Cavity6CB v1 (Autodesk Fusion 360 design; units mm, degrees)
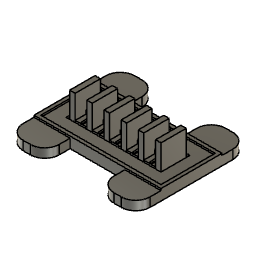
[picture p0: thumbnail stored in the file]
sketch "Sketch1" plane through (0, 0, 0) normal (0, 0, 1) x axis (1, 0, 0)
  line L1 (3, 0) -> (0, 0)
  line L2 (3, 14) -> (3, 0)
  line L3 (0, 14) -> (3, 14)
  line L4 (0, 0) -> (0, 14)
  line L5 (9.5, 14) -> (3, 14)
  line L6 (9.5, 0) -> (9.5, 14)
  line L7 (3, 0) -> (9.5, 0)
  line L8 (9.5, 8) -> (3, 8)
  line L9 (3, 6) -> (3, 8)
  line L10 (9.5, 6) -> (3, 6)
  line L11 (9.5, 6) -> (9.5, 8)
  line L12 (7, 5.5) -> (5.5, 5.5)
  line L13 (7, 0.7) -> (7, 5.5)
  line L14 (5.5, 0.7) -> (7, 0.7)
  line L15 (5.5, 5.5) -> (5.5, 0.7)
  line L16 (12.5, 0) -> (9.5, 0)
  line L17 (12.5, 14) -> (12.5, 0)
  line L18 (9.5, 14) -> (12.5, 14)
  line L19 (9.5, 0) -> (9.5, 14)
  line L20 (19, 14) -> (12.5, 14)
  line L21 (19, 0) -> (19, 14)
  line L22 (12.5, 0) -> (19, 0)
  line L23 (19, 8) -> (12.5, 8)
  line L24 (19, 6) -> (19, 8)
  line L25 (19, 6) -> (12.5, 6)
  line L26 (12.5, 6) -> (12.5, 8)
  line L27 (16.5, 5.5) -> (15, 5.5)
  line L28 (16.5, 0.7) -> (16.5, 5.5)
  line L29 (15, 0.7) -> (16.5, 0.7)
  line L30 (15, 5.5) -> (15, 0.7)
  line L31 (22, 14) -> (19, 14)
  line L32 (22, 0) -> (22, 14)
  line L33 (19, 0) -> (22, 0)
  line L34 (19, 14) -> (19, 0)
  line L35 (28.5, 14) -> (22, 14)
  line L36 (28.5, 0) -> (28.5, 14)
  line L37 (22, 0) -> (28.5, 0)
  line L38 (28.5, 8) -> (22, 8)
  line L39 (28.5, 6) -> (28.5, 8)
  line L40 (22, 6) -> (28.5, 6)
  line L41 (22, 6) -> (22, 8)
  line L42 (26, 0.7) -> (24.5, 0.7)
  line L43 (26, 5.5) -> (26, 0.7)
  line L44 (24.5, 5.5) -> (26, 5.5)
  line L45 (24.5, 0.7) -> (24.5, 5.5)
  line L46 (31.5, 14) -> (28.5, 14)
  line L47 (31.5, 0) -> (31.5, 14)
  line L48 (28.5, 0) -> (31.5, 0)
  line L49 (28.5, 14) -> (28.5, 0)
  line L50 (38, 14) -> (31.5, 14)
  line L51 (38, 0) -> (38, 14)
  line L52 (31.5, 0) -> (38, 0)
  line L53 (38, 8) -> (31.5, 8)
  line L54 (38, 6) -> (38, 8)
  line L55 (31.5, 6) -> (38, 6)
  line L56 (31.5, 6) -> (31.5, 8)
  line L57 (35.5, 0.7) -> (34, 0.7)
  line L58 (35.5, 5.5) -> (35.5, 0.7)
  line L59 (34, 5.5) -> (35.5, 5.5)
  line L60 (34, 0.7) -> (34, 5.5)
  line L61 (41, 14) -> (38, 14)
  line L62 (41, 0) -> (41, 14)
  line L63 (38, 0) -> (41, 0)
  line L64 (38, 14) -> (38, 0)
  line L65 (47.5, 14) -> (41, 14)
  line L66 (47.5, 0) -> (47.5, 14)
  line L67 (41, 0) -> (47.5, 0)
  line L68 (47.5, 8) -> (41, 8)
  line L69 (47.5, 6) -> (47.5, 8)
  line L70 (41, 6) -> (47.5, 6)
  line L71 (41, 8) -> (41, 6)
  line L72 (45, 5.5) -> (43.5, 5.5)
  line L73 (45, 0.7) -> (45, 5.5)
  line L74 (43.5, 0.7) -> (45, 0.7)
  line L75 (43.5, 5.5) -> (43.5, 0.7)
  line L76 (50.5, 14) -> (47.5, 14)
  line L77 (50.5, 0) -> (50.5, 14)
  line L78 (47.5, 0) -> (50.5, 0)
  line L79 (47.5, 14) -> (47.5, 0)
  line L80 (57.5588, 7) -> (-12, 7)
  line L81 (7, 8.5) -> (5.5, 8.5)
  line L82 (5.5, 8.5) -> (5.5, 13.3)
  line L83 (5.5, 13.3) -> (7, 13.3)
  line L84 (7, 13.3) -> (7, 8.5)
  line L85 (16.5, 8.5) -> (15, 8.5)
  line L86 (15, 8.5) -> (15, 13.3)
  line L87 (15, 13.3) -> (16.5, 13.3)
  line L88 (16.5, 13.3) -> (16.5, 8.5)
  line L89 (24.5, 8.5) -> (26, 8.5)
  line L90 (24.5, 13.3) -> (24.5, 8.5)
  line L91 (26, 13.3) -> (24.5, 13.3)
  line L92 (26, 8.5) -> (26, 13.3)
  line L93 (34, 8.5) -> (35.5, 8.5)
  line L94 (34, 13.3) -> (34, 8.5)
  line L95 (35.5, 13.3) -> (34, 13.3)
  line L96 (35.5, 8.5) -> (35.5, 13.3)
  line L97 (45, 8.5) -> (43.5, 8.5)
  line L98 (43.5, 8.5) -> (43.5, 13.3)
  line L99 (45, 13.3) -> (45, 8.5)
  line L100 (43.5, 13.3) -> (45, 13.3)
  line L101 (50.5, 0) -> (0, 0)
  line L102 (50.5, 14) -> (50.5, 0)
  line L103 (0, 14) -> (50.5, 14)
  line L104 (0, 0) -> (0, 14)
  line L105 (-1, 15) -> (51.5, 15)
  line L106 (-1, -1) -> (-1, 15)
  line L107 (51.5, -1) -> (-1, -1)
  line L108 (51.5, 15) -> (51.5, -1)
  line L109 (58.5, -8) -> (-8, -8)
  line L110 (58.5, 22) -> (58.5, -8)
  line L111 (-8, 22) -> (58.5, 22)
  line L112 (-8, -8) -> (-8, 22)
  line L113 (60.4, -9.9) -> (-9.9, -9.9)
  line L114 (60.4, 23.9) -> (60.4, -9.9)
  line L115 (-9.9, 23.9) -> (60.4, 23.9)
  line L116 (-9.9, -9.9) -> (-9.9, 23.9)
  point P1 (0, 0)
  point P2 (0, 0)
  point P8 (3, 8)
  point P9 (9.5, 8)
  point P10 (3, 6)
  point P11 (9.5, 6)
  point P21 (12.5, 8)
  point P23 (19, 6)
  point P24 (12.5, 6)
  point P34 (22, 8)
  point P35 (28.5, 8)
  point P36 (28.5, 6)
  point P37 (22, 6)
  point P47 (31.5, 8)
  point P48 (38, 8)
  point P49 (38, 6)
  point P50 (31.5, 6)
  point P60 (41, 8)
  point P61 (47.5, 8)
  point P62 (47.5, 6)
  point P63 (41, 6)
  point P12 (5.5, 5.5)
  point P73 (5.5, 8.5)
  point P13 (7, 5.5)
  point P74 (7, 8.5)
  point P14 (7, 0.7)
  point P76 (7, 13.3)
  point P15 (5.5, 0.7)
  point P75 (5.5, 13.3)
  point P25 (15, 5.5)
  point P77 (15, 8.5)
  point P26 (16.5, 5.5)
  point P78 (16.5, 8.5)
  point P27 (16.5, 0.7)
  point P80 (16.5, 13.3)
  point P28 (15, 0.7)
  point P79 (15, 13.3)
  point P38 (24.5, 0.7)
  point P83 (24.5, 13.3)
  point P39 (26, 0.7)
  point P84 (26, 13.3)
  point P40 (26, 5.5)
  point P81 (26, 8.5)
  point P41 (24.5, 5.5)
  point P82 (24.5, 8.5)
  point P51 (34, 0.7)
  point P87 (34, 13.3)
  point P52 (35.5, 0.7)
  point P88 (35.5, 13.3)
  point P53 (35.5, 5.5)
  point P85 (35.5, 8.5)
  point P54 (34, 5.5)
  point P86 (34, 8.5)
  point P64 (43.5, 5.5)
  point P89 (43.5, 8.5)
  point P65 (45, 5.5)
  point P90 (45, 8.5)
  point P66 (45, 0.7)
  point P92 (45, 13.3)
  point P67 (43.5, 0.7)
  point P91 (43.5, 13.3)
  point P93 (0, 0)
  point P3 (3, 0)
  point P5 (0, 14)
  point P4 (3, 14)
  point P6 (9.5, 14)
  point P7 (9.5, 0)
  point P16 (12.5, 0)
  point P18 (9.5, 14)
  point P17 (12.5, 14)
  point P19 (19, 14)
  point P29 (22, 14)
  point P32 (28.5, 14)
  point P42 (31.5, 14)
  point P45 (38, 14)
  point P55 (41, 14)
  point P58 (47.5, 14)
  point P68 (50.5, 14)
  point P70 (47.5, 0)
  horizontal L1
  vertical L2
  horizontal L3
  vertical L4
  coincident P1 P2
  perpendicular L2 L5
  perpendicular L3 L6
  perpendicular L2 L7
  coincident L2 P8
  coincident L6 P9
  perpendicular L6 L8
  coincident L2 P10
  coincident L6 P11
  perpendicular L6 L10
  horizontal L12
  vertical L13
  horizontal L14
  vertical L15
  horizontal L16
  vertical L17
  horizontal L18
  vertical L19
  perpendicular L17 L20
  perpendicular L20 L21
  perpendicular L17 L22
  coincident L17 P21
  perpendicular L17 L23
  coincident L21 P23
  perpendicular L23 L24
  coincident L17 P24
  perpendicular L21 L25
  horizontal L27
  vertical L28
  horizontal L29
  vertical L30
  horizontal L31
  vertical L32
  horizontal L33
  vertical L34
  perpendicular L32 L35
  perpendicular L31 L36
  perpendicular L32 L37
  coincident L32 P34
  coincident L36 P35
  perpendicular L36 L38
  coincident L36 P36
  coincident L32 P37
  perpendicular L32 L40
  horizontal L42
  vertical L43
  horizontal L44
  vertical L45
  horizontal L46
  vertical L47
  horizontal L48
  vertical L49
  perpendicular L47 L50
  perpendicular L46 L51
  perpendicular L47 L52
  coincident L47 P47
  coincident L51 P48
  perpendicular L51 L53
  coincident L51 P49
  coincident L47 P50
  perpendicular L47 L55
  horizontal L57
  vertical L58
  horizontal L59
  vertical L60
  horizontal L61
  vertical L62
  horizontal L63
  vertical L64
  perpendicular L62 L65
  perpendicular L61 L66
  perpendicular L62 L67
  coincident L62 P60
  coincident L66 P61
  perpendicular L66 L68
  coincident L66 P62
  coincident L62 P63
  perpendicular L62 L70
  horizontal L72
  vertical L73
  horizontal L74
  vertical L75
  horizontal L76
  vertical L77
  horizontal L78
  vertical L79
  perpendicular L69 L80
  symmetric P12 L80 P73
  symmetric P13 L80 P74
  symmetric P14 L80 P76
  symmetric P15 L80 P75
  symmetric P25 L80 P77
  symmetric P26 L80 P78
  symmetric P27 L80 P80
  symmetric P28 L80 P79
  symmetric P38 L80 P83
  symmetric P39 L80 P84
  symmetric P40 L80 P81
  symmetric P41 L80 P82
  symmetric P51 L80 P87
  symmetric P52 L80 P88
  symmetric P53 L80 P85
  symmetric P54 L80 P86
  symmetric P64 L80 P89
  symmetric P65 L80 P90
  symmetric P66 L80 P92
  symmetric P67 L80 P91
  horizontal L101
  vertical L102
  horizontal L103
  vertical L104
  coincident P1 P93
  horizontal L109
  vertical L110
  horizontal L111
  vertical L112
  dimension "d1" distance P2 P3 = 3
  dimension "d2" distance P2 P5 = 14
  dimension "d3" distance P4 P6 = 6.5
  dimension "d4" distance L5 L8 = 6
  dimension "d5" distance P8 P10 = 2
  dimension "d6" distance L10 L12 = 0.5
  dimension "d7" distance L7 L14 = 0.7
  dimension "d8" distance L2 L15 = 2.5
  dimension "d9" distance L6 L13 = 2.5
  dimension "d10" distance P7 P16 = 3
  dimension "d11" distance P7 P18 = 14
  dimension "d12" distance P17 P19 = 6.5
  dimension "d13" distance L25 L27 = 0.5
  dimension "d14" distance L21 L28 = 2.5
  dimension "d15" distance L17 L30 = 2.5
  dimension "d16" distance L22 L29 = 0.7
  dimension "d17" distance P29 P32 = 6.5
  dimension "d18" distance L40 L44 = 0.5
  dimension "d19" distance L36 L43 = 2.5
  dimension "d20" distance L32 L45 = 2.5
  dimension "d21" distance L37 L42 = 0.7
  dimension "d22" distance P32 P42 = 3
  dimension "d23" distance P42 P45 = 6.5
  dimension "d24" distance L55 L59 = 0.5
  dimension "d25" distance L51 L58 = 2.5
  dimension "d26" distance L47 L60 = 2.5
  dimension "d27" distance L52 L57 = 0.7
  dimension "d28" distance P55 P58 = 6.5
  dimension "d29" distance L70 L72 = 0.5
  dimension "d30" distance L67 L74 = 0.7
  dimension "d31" distance L62 L75 = 2.5
  dimension "d32" distance L66 L73 = 2.5
  dimension "d33" distance P58 P68 = 3
  dimension "d34" distance P58 P70 = 14
  dimension "d35" distance L3 L80 = 7
  dimension "d36" = 1
  dimension "d37" distance L105 L111 = 7
  dimension "d38" distance L108 L110 = 7
  dimension "d39" distance L107 L109 = 7
  dimension "d40" distance L106 L112 = 7
  dimension "d41" = 1.9
extrude "Extrude1" new body sketch "Sketch1" against normal blind 5
extrude "Extrude2" cut sketch "Sketch1" profile of L1 L2 L3 L4 L5 L6 L7 L9 L11 L12 L13 L14 L15 L16 L17 L18 L19 L20 L21 L22 L24 L26 L27 L28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 against normal blind 1
extrude "Extrude3" add sketch "Sketch1" profile of L2 L6 L8 L9 L10 L11 L17 L19 L21 L23 L24 L25 L26 L32 L34 L36 L38 L39 L40 L41 L47 L49 L51 L53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 along normal blind 2
extrude "Extrude4" new body sketch "Sketch1" profile of L1 L2 L3 L4 L6 L9 L11 L16 L17 L18 L19 L21 L24 L26 L31 L32 L33 L34 L36 L39 L41 L46 L47 L48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 along normal blind 13 and against normal blind 1
extrude "Extrude5" add sketch "Sketch1" profile of L109 L110 L111 L112 L115 L113 L114 L116 along normal blind 1
sketch "Sketch2" plane through (0, -9.9, 0) normal (0, -1, 0) x axis (1, 0, 0)
  line L1 (-9.9, -5) -> (-9.9, 1)
  line L2 (60.4, -5) -> (-9.9, -5)
  line L3 (60.4, 1) -> (60.4, -5)
  line L4 (-9.9, 1) -> (60.4, 1)
  line L5 (10.1, -5) -> (-9.9, -5)
  line L6 (10.1, 0) -> (10.1, -5)
  line L7 (-9.9, 0) -> (10.1, 0)
  line L8 (-9.9, -5) -> (-9.9, 0)
  line L9 (40.4, -5) -> (60.4, -5)
  line L10 (40.4, 0) -> (40.4, -5)
  line L11 (60.4, 0) -> (40.4, 0)
  line L12 (60.4, -5) -> (60.4, 0)
  point P3 (-9.9, -5)
  point P6 (-9.9, -5)
  point P4 (60.4, -5)
  point P10 (60.4, -5)
  point P7 (10.1, -5)
  point P11 (40.4, -5)
  point P13 (60.4, 0)
  horizontal L5
  vertical L6
  horizontal L7
  vertical L8
  coincident P3 P6
  horizontal L9
  vertical L10
  horizontal L11
  vertical L12
  coincident P4 P10
  dimension "d54" distance P6 P7 = 20
  dimension "d55" distance P10 P11 = 20
  dimension "d56" distance P10 P13 = 5
extrude "Extrude6" add sketch "Sketch2" profile of L1 L2 L3 L5 L6 L7 L8 L9 L10 L11 L12 along normal blind 14
fillet "Fillet1" radius 8
sketch "Sketch3" plane through (0, 23.9, 0) normal (0, 1, 0) x axis (-1, 0, 0)
  line L1 (-60.4, -5) -> (-60.4, 1)
  line L2 (9.9, -5) -> (-60.4, -5)
  line L3 (9.9, 1) -> (9.9, -5)
  line L4 (-60.4, 1) -> (9.9, 1)
  line L5 (-40.4, -5) -> (-60.4, -5)
  line L6 (-40.4, 0) -> (-40.4, -5)
  line L7 (-60.4, 0) -> (-40.4, 0)
  line L8 (-60.4, -5) -> (-60.4, 0)
  line L9 (-10.1, -5) -> (9.9, -5)
  line L10 (-10.1, 0) -> (-10.1, -5)
  line L11 (9.9, 0) -> (-10.1, 0)
  line L12 (9.9, -5) -> (9.9, 0)
  point P3 (-60.4, -5)
  point P6 (-60.4, -5)
  point P4 (9.9, -5)
  point P10 (9.9, -5)
  point P7 (-40.4, -5)
  point P9 (-60.4, 0)
  point P11 (-10.1, -5)
  point P13 (9.9, 0)
  horizontal L5
  vertical L6
  horizontal L7
  vertical L8
  coincident P3 P6
  horizontal L9
  vertical L10
  horizontal L11
  vertical L12
  coincident P4 P10
  dimension "d61" distance P6 P7 = 20
  dimension "d62" distance P6 P9 = 5
  dimension "d63" distance P10 P11 = 20
  dimension "d64" distance P10 P13 = 5
extrude "Extrude7" add sketch "Sketch3" profile of L1 L2 L3 L5 L6 L7 L8 L9 L10 L11 L12 along normal blind 14
fillet "Fillet2" radius 8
